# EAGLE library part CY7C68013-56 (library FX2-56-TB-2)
FX2
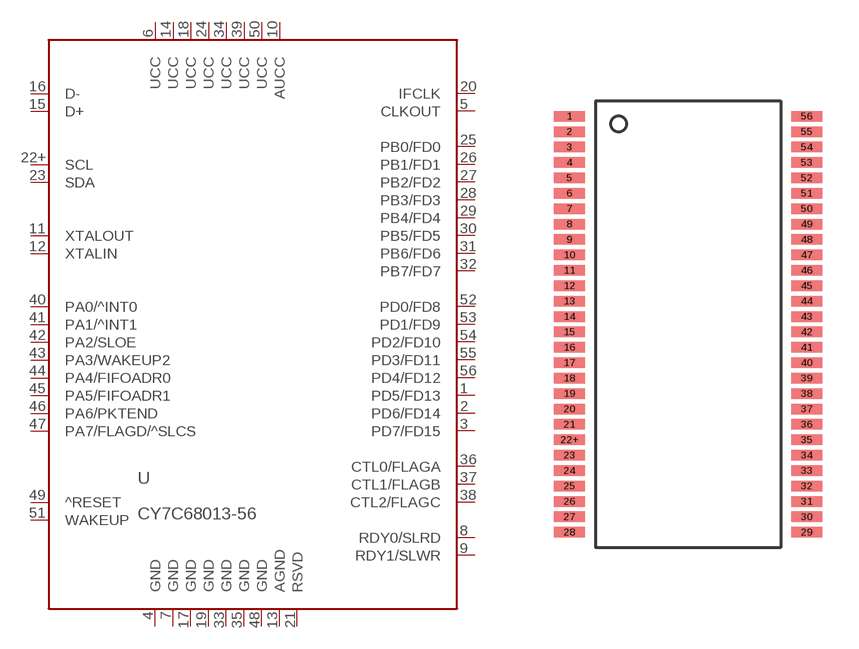
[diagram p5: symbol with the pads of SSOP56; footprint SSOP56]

Designator prefix U

## CY7C68013-56PVC  [SSOP56]
1  PD5/FD13
2  PD6/FD14
3  PD7/FD15
4  GND  pwr
5  CLKOUT  hiz
6  UCC  pwr
7  GND  pwr
8  RDY0/SLRD  in
9  RDY1/SLWR  in
10  AUCC  pwr
11  XTALOUT  out
12  XTALIN  in
13  AGND  pwr
14  UCC  pwr
15  D+
16  D-
17  GND  pwr
18  UCC  pwr
19  GND  pwr
20  IFCLK
21  RSVD  in
22+  SCL  oc
23  SDA  oc
24  UCC  pwr
25  PB0/FD0
26  PB1/FD1
27  PB2/FD2
28  PB3/FD3
29  PB4/FD4
30  PB5/FD5
31  PB6/FD6
32  PB7/FD7
33  GND  pwr
34  UCC  pwr
35  GND  pwr
36  CTL0/FLAGA  hiz
37  CTL1/FLAGB  hiz
38  CTL2/FLAGC  hiz
39  UCC  pwr
40  PA0/^INT0
41  PA1/^INT1
42  PA2/SLOE
43  PA3/WAKEUP2
44  PA4/FIFOADR0
45  PA5/FIFOADR1
46  PA6/PKTEND
47  PA7/FLAGD/^SLCS
48  GND  pwr
49  ^RESET  in
50  UCC  pwr
51  WAKEUP  in
52  PD0/FD8
53  PD1/FD9
54  PD2/FD10
55  PD3/FD11
56  PD4/FD12

## Footprint SSOP56 (pad centres in mm)
56-lead Shrunk Small Outline Package O56 Raster: 25 mil (0,65 mm)
smd 1.27 x 0.432: 1 -4.889,8.572; 2 -4.889,7.938; 3 -4.889,7.303; 4 -4.889,6.668; 5 -4.889,6.032; 6 -4.889,5.397; 7 -4.889,4.763; 8 -4.889,4.128; 9 -4.889,3.493; 10 -4.889,2.857; 11 -4.889,2.223; 12 -4.889,1.587; 13 -4.889,0.953; 14 -4.889,0.318; 15 -4.889,-0.318; 16 -4.889,-0.953; 17 -4.889,-1.587; 18 -4.889,-2.223; 19 -4.889,-2.857; 20 -4.889,-3.493; 21 -4.889,-4.128; 22+ -4.889,-4.763; 23 -4.889,-5.397; 24 -4.889,-6.032; 25 -4.889,-6.668; 26 -4.889,-7.303; 27 -4.889,-7.938; 28 -4.889,-8.572; 29 4.889,-8.572; 30 4.889,-7.938; 31 4.889,-7.303; 32 4.889,-6.668; 33 4.889,-6.032; 34 4.889,-5.397; 35 4.889,-4.763; 36 4.889,-4.128; 37 4.889,-3.493; 38 4.889,-2.857; 39 4.889,-2.223; 40 4.889,-1.587; 41 4.889,-0.953; 42 4.889,-0.318; 43 4.889,0.318; 44 4.889,0.953; 45 4.889,1.587; 46 4.889,2.223; 47 4.889,2.857; 48 4.889,3.493; 49 4.889,4.128; 50 4.889,4.763; 51 4.889,5.397; 52 4.889,6.032; 53 4.889,6.668; 54 4.889,7.303; 55 4.889,7.938; 56 4.889,8.572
